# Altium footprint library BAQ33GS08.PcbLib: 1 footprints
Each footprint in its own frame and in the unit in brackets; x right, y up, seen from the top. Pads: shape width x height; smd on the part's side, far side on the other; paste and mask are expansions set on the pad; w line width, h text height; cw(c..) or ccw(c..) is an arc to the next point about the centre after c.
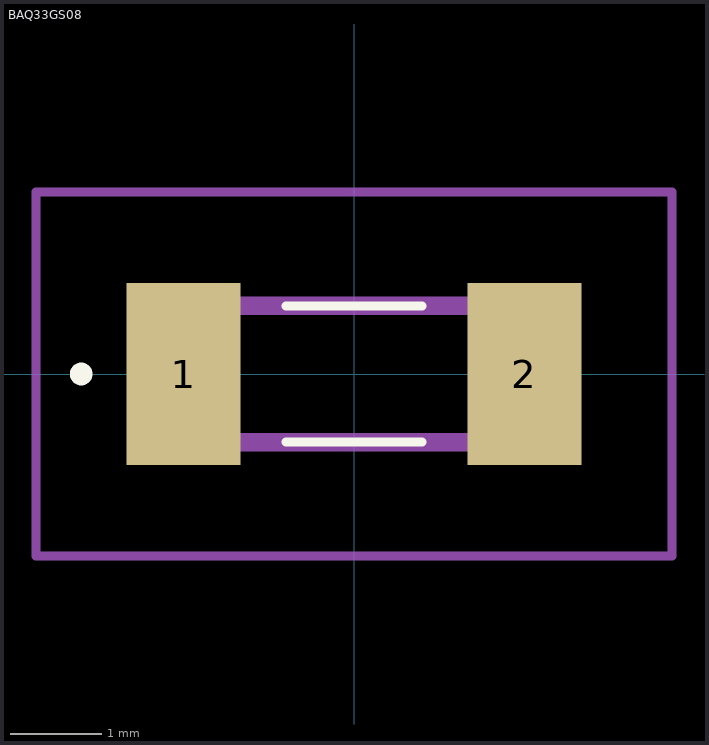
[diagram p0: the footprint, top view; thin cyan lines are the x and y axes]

## BAQ33GS08 [mm]
pads (2):
  rect 1.25x2 smd: 1(-1.875,0) 2(1.875,0)
Top Overlay:
  lines w0.1: -0.75,-0.75 0.75,-0.75 ; -0.75,0.75 0.75,0.75
  lines w0.125: -3.063,0 -3.063,0 ; -3.062,-0.001 cw(c-3,-0.001) -2.939,-0.001 cw(c-3,0.001) -3.062,0.001 ; -2.938,0 -2.938,0
Mechanical 15:
  lines w0.1: -1.5,-0.75 -1.5,0.75
  lines w0.2: -1.75,-0.75 1.75,-0.75 1.75,0.75 -1.75,0.75 -1.75,-0.75
Mechanical 20:
  lines w0.1: -3.5,-2 3.5,-2 3.5,2 -3.5,2 -3.5,-2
